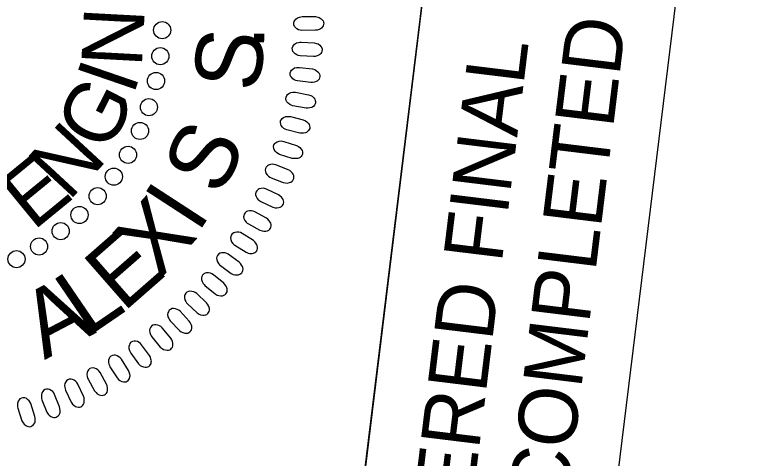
# Model space of a CAD drawing. Extents: x 480570 to 481861, y 488765 to 490569.
# Drawn here: x 480900.2 to 480970.2, y 490446 to 490487.4 of the extents above; entities that cross this region are included whole.
import ezdxf

# ---------------------------------------------------------------- set-up
doc = ezdxf.new("R2010")
doc.units = 0
for name, color, linetype in [('Sheet PE Seal Cell', 7, 'Continuous'), ('Sheet Plan CELL', 7, 'Continuous'), ('Sheet Sticker Exception Certification CELL', 7, 'Continuous')]:
    doc.layers.add(name, color=color, linetype=linetype)

msp = doc.modelspace()

# ---------------------------------------------------------------- linework, layer by layer
at = {"layer": 'Sheet PE Seal Cell'}
for points in [[(480927.001, 490487.259), (480928.228, 490487.263), (480928.447, 490487.227), (480928.587, 490487.176), (480928.758, 490487.064), (480928.867, 490486.967), (480928.948, 490486.855), (480928.988, 490486.751), (480929.008, 490486.638), (480928.988, 490486.527), (480928.959, 490486.407), (480928.9, 490486.302), (480928.8, 490486.197), (480928.721, 490486.137), (480928.571, 490486.069), (480928.392, 490486.008), (480928.233, 490485.985), (480926.976, 490485.973), (480926.807, 490485.995), (480926.667, 490486.04), (480926.507, 490486.129), (480926.367, 490486.239), (480926.286, 490486.337), (480926.226, 490486.494), (480926.206, 490486.644), (480926.245, 490486.793), (480926.295, 490486.898), (480926.394, 490487.025), (480926.562, 490487.145), (480926.743, 490487.213), (480926.871, 490487.243)], [(480926.906, 490484.887), (480928.131, 490484.814), (480928.348, 490484.765), (480928.484, 490484.705), (480928.647, 490484.582), (480928.751, 490484.479), (480928.824, 490484.362), (480928.857, 490484.256), (480928.87, 490484.142), (480928.844, 490484.032), (480928.807, 490483.914), (480928.741, 490483.813), (480928.635, 490483.714), (480928.552, 490483.659), (480928.399, 490483.601), (480928.216, 490483.552), (480928.055, 490483.539), (480926.801, 490483.605), (480926.633, 490483.638), (480926.496, 490483.691), (480926.342, 490483.791), (480926.209, 490483.91), (480926.136, 490484.012), (480926.085, 490484.172), (480926.074, 490484.323), (480926.123, 490484.469), (480926.179, 490484.571), (480926.285, 490484.692), (480926.462, 490484.801), (480926.645, 490484.858), (480926.776, 490484.88)], [(480926.741, 490482.523), (480927.959, 490482.373), (480928.171, 490482.31), (480928.304, 490482.241), (480928.459, 490482.109), (480928.556, 490481.999), (480928.622, 490481.878), (480928.648, 490481.77), (480928.654, 490481.656), (480928.621, 490481.547), (480928.577, 490481.432), (480928.505, 490481.335), (480928.393, 490481.243), (480928.306, 490481.194), (480928.149, 490481.145), (480927.964, 490481.107), (480927.803, 490481.105), (480926.555, 490481.25), (480926.39, 490481.293), (480926.256, 490481.355), (480926.109, 490481.463), (480925.984, 490481.591), (480925.916, 490481.698), (480925.876, 490481.861), (480925.875, 490482.012), (480925.932, 490482.155), (480925.995, 490482.253), (480926.109, 490482.368), (480926.292, 490482.465), (480926.479, 490482.51), (480926.611, 490482.523)], [(480926.384, 490480.196), (480927.59, 490479.97), (480927.798, 490479.893), (480927.927, 490479.816), (480928.073, 490479.675), (480928.163, 490479.559), (480928.22, 490479.435), (480928.241, 490479.324), (480928.239, 490479.209), (480928.199, 490479.104), (480928.148, 490478.992), (480928.07, 490478.9), (480927.952, 490478.815), (480927.863, 490478.771), (480927.704, 490478.732), (480927.516, 490478.706), (480927.355, 490478.714), (480926.119, 490478.937), (480925.956, 490478.99), (480925.827, 490479.06), (480925.687, 490479.178), (480925.57, 490479.313), (480925.51, 490479.424), (480925.48, 490479.589), (480925.488, 490479.74), (480925.555, 490479.88), (480925.623, 490479.973), (480925.744, 490480.08), (480925.933, 490480.166), (480926.122, 490480.199), (480926.254, 490480.204)], [(480925.907, 490477.919), (480927.096, 490477.619), (480927.3, 490477.529), (480927.423, 490477.444), (480927.56, 490477.294), (480927.642, 490477.172), (480927.692, 490477.044), (480927.705, 490476.933), (480927.697, 490476.819), (480927.65, 490476.716), (480927.592, 490476.607), (480927.508, 490476.52), (480927.385, 490476.444), (480927.293, 490476.405), (480927.132, 490476.376), (480926.943, 490476.362), (480926.783, 490476.379), (480925.563, 490476.68), (480925.405, 490476.743), (480925.28, 490476.822), (480925.147, 490476.947), (480925.039, 490477.09), (480924.986, 490477.204), (480924.966, 490477.371), (480924.984, 490477.521), (480925.059, 490477.656), (480925.133, 490477.745), (480925.261, 490477.844), (480925.454, 490477.918), (480925.645, 490477.939), (480925.778, 490477.937)], [(480925.296, 490475.61), (480926.465, 490475.235), (480926.662, 490475.133), (480926.779, 490475.041), (480926.906, 490474.882), (480926.981, 490474.756), (480927.023, 490474.625), (480927.029, 490474.513), (480927.013, 490474.4), (480926.96, 490474.3), (480926.895, 490474.195), (480926.806, 490474.113), (480926.679, 490474.044), (480926.585, 490474.012), (480926.422, 490473.993), (480926.233, 490473.991), (480926.074, 490474.018), (480924.875, 490474.395), (480924.72, 490474.469), (480924.602, 490474.554), (480924.477, 490474.688), (480924.378, 490474.837), (480924.332, 490474.954), (480924.323, 490475.122), (480924.35, 490475.271), (480924.434, 490475.4), (480924.513, 490475.485), (480924.646, 490475.576), (480924.844, 490475.637), (480925.036, 490475.647), (480925.168, 490475.635)], [(480924.087, 490472.21), (480925.23, 490471.762), (480925.447, 490471.718), (480925.596, 490471.715), (480925.796, 490471.758), (480925.933, 490471.808), (480926.048, 490471.884), (480926.124, 490471.966), (480926.183, 490472.063), (480926.205, 490472.175), (480926.22, 490472.298), (480926.204, 490472.416), (480926.149, 490472.55), (480926.097, 490472.635), (480925.981, 490472.752), (480925.836, 490472.874), (480925.695, 490472.953), (480924.528, 490473.418), (480924.362, 490473.459), (480924.216, 490473.467), (480924.034, 490473.442), (480923.864, 490473.389), (480923.754, 490473.327), (480923.641, 490473.203), (480923.568, 490473.071), (480923.55, 490472.917), (480923.559, 490472.802), (480923.605, 490472.647), (480923.72, 490472.474), (480923.863, 490472.346), (480923.972, 490472.271)], [(480923.136, 490469.976), (480924.248, 490469.458), (480924.463, 490469.399), (480924.612, 490469.387), (480924.813, 490469.417), (480924.953, 490469.459), (480925.073, 490469.527), (480925.153, 490469.605), (480925.219, 490469.698), (480925.248, 490469.808), (480925.271, 490469.93), (480925.262, 490470.049), (480925.215, 490470.187), (480925.168, 490470.274), (480925.061, 490470.399), (480924.923, 490470.528), (480924.788, 490470.616), (480923.653, 490471.154), (480923.489, 490471.205), (480923.343, 490471.223), (480923.161, 490471.209), (480922.988, 490471.167), (480922.874, 490471.112), (480922.753, 490470.996), (480922.672, 490470.868), (480922.645, 490470.716), (480922.647, 490470.6), (480922.683, 490470.443), (480922.786, 490470.263), (480922.921, 490470.126), (480923.025, 490470.044)], [(480921.973, 490467.893), (480923.05, 490467.306), (480923.261, 490467.234), (480923.408, 490467.212), (480923.611, 490467.23), (480923.754, 490467.263), (480923.877, 490467.324), (480923.963, 490467.396), (480924.034, 490467.485), (480924.07, 490467.593), (480924.101, 490467.713), (480924.099, 490467.833), (480924.061, 490467.972), (480924.019, 490468.063), (480923.92, 490468.194), (480923.791, 490468.332), (480923.662, 490468.429), (480922.562, 490469.036), (480922.403, 490469.098), (480922.258, 490469.124), (480922.076, 490469.122), (480921.899, 490469.091), (480921.782, 490469.043), (480921.655, 490468.935), (480921.566, 490468.812), (480921.53, 490468.662), (480921.524, 490468.546), (480921.55, 490468.387), (480921.642, 490468.201), (480921.767, 490468.056), (480921.867, 490467.968)], [(480920.714, 490465.903), (480921.752, 490465.25), (480921.958, 490465.165), (480922.104, 490465.135), (480922.307, 490465.139), (480922.452, 490465.163), (480922.579, 490465.215), (480922.668, 490465.282), (480922.745, 490465.367), (480922.788, 490465.473), (480922.826, 490465.59), (480922.831, 490465.71), (480922.803, 490465.852), (480922.767, 490465.945), (480922.676, 490466.082), (480922.557, 490466.228), (480922.433, 490466.332), (480921.374, 490467.008), (480921.218, 490467.079), (480921.076, 490467.115), (480920.893, 490467.125), (480920.715, 490467.104), (480920.596, 490467.064), (480920.462, 490466.963), (480920.365, 490466.847), (480920.319, 490466.7), (480920.306, 490466.584), (480920.322, 490466.424), (480920.402, 490466.233), (480920.519, 490466.079), (480920.612, 490465.986)], [(480919.366, 490463.993), (480920.361, 490463.276), (480920.561, 490463.178), (480920.705, 490463.139), (480920.908, 490463.131), (480921.054, 490463.145), (480921.184, 490463.19), (480921.278, 490463.251), (480921.36, 490463.331), (480921.408, 490463.433), (480921.454, 490463.547), (480921.468, 490463.667), (480921.447, 490463.811), (480921.418, 490463.905), (480921.336, 490464.048), (480921.225, 490464.201), (480921.109, 490464.313), (480920.093, 490465.054), (480919.943, 490465.134), (480919.803, 490465.18), (480919.622, 490465.2), (480919.443, 490465.191), (480919.321, 490465.159), (480919.181, 490465.067), (480919.077, 490464.957), (480919.022, 490464.813), (480919.001, 490464.698), (480919.008, 490464.537), (480919.076, 490464.341), (480919.182, 490464.181), (480919.269, 490464.081)], [(480917.914, 490462.138), (480918.863, 490461.359), (480919.056, 490461.249), (480919.197, 490461.201), (480919.4, 490461.179), (480919.546, 490461.185), (480919.678, 490461.222), (480919.776, 490461.276), (480919.862, 490461.351), (480919.918, 490461.45), (480919.971, 490461.562), (480919.991, 490461.68), (480919.981, 490461.825), (480919.957, 490461.922), (480919.884, 490462.069), (480919.783, 490462.228), (480919.674, 490462.347), (480918.708, 490463.15), (480918.562, 490463.24), (480918.426, 490463.294), (480918.246, 490463.326), (480918.067, 490463.328), (480917.943, 490463.303), (480917.797, 490463.221), (480917.687, 490463.117), (480917.623, 490462.976), (480917.595, 490462.864), (480917.591, 490462.703), (480917.646, 490462.503), (480917.743, 490462.336), (480917.824, 490462.231)], [(480916.281, 490460.421), (480917.179, 490459.585), (480917.365, 490459.463), (480917.503, 490459.406), (480917.703, 490459.372), (480917.85, 490459.369), (480917.985, 490459.396), (480918.085, 490459.445), (480918.176, 490459.514), (480918.238, 490459.61), (480918.297, 490459.718), (480918.326, 490459.835), (480918.323, 490459.98), (480918.306, 490460.078), (480918.242, 490460.229), (480918.152, 490460.395), (480918.051, 490460.52), (480917.136, 490461.382), (480916.997, 490461.482), (480916.864, 490461.544), (480916.687, 490461.587), (480916.508, 490461.601), (480916.383, 490461.584), (480916.232, 490461.51), (480916.115, 490461.414), (480916.043, 490461.277), (480916.009, 490461.166), (480915.994, 490461.006), (480916.037, 490460.803), (480916.123, 490460.631), (480916.197, 490460.521)], [(480914.675, 490458.824), (480915.518, 490457.932), (480915.696, 490457.799), (480915.83, 490457.733), (480916.028, 490457.687), (480916.174, 490457.675), (480916.31, 490457.693), (480916.414, 490457.736), (480916.51, 490457.799), (480916.576, 490457.89), (480916.643, 490457.994), (480916.678, 490458.109), (480916.685, 490458.254), (480916.674, 490458.353), (480916.62, 490458.508), (480916.54, 490458.679), (480916.447, 490458.811), (480915.588, 490459.729), (480915.456, 490459.837), (480915.326, 490459.907), (480915.152, 490459.961), (480914.975, 490459.986), (480914.849, 490459.977), (480914.694, 490459.912), (480914.572, 490459.824), (480914.491, 490459.692), (480914.449, 490459.584), (480914.425, 490459.424), (480914.455, 490459.219), (480914.529, 490459.042), (480914.597, 490458.928)], [(480912.951, 490457.332), (480913.737, 490456.389), (480913.906, 490456.245), (480914.035, 490456.171), (480914.23, 490456.113), (480914.376, 490456.09), (480914.512, 490456.101), (480914.618, 490456.137), (480914.717, 490456.194), (480914.79, 490456.281), (480914.863, 490456.381), (480914.905, 490456.493), (480914.921, 490456.637), (480914.917, 490456.736), (480914.873, 490456.895), (480914.803, 490457.071), (480914.719, 490457.208), (480913.919, 490458.178), (480913.794, 490458.294), (480913.67, 490458.372), (480913.499, 490458.437), (480913.324, 490458.473), (480913.198, 490458.472), (480913.039, 490458.418), (480912.911, 490458.337), (480912.822, 490458.21), (480912.774, 490458.105), (480912.739, 490457.947), (480912.756, 490457.741), (480912.82, 490457.559), (480912.88, 490457.44)], [(480910.975, 490455.825), (480911.7, 490454.835), (480911.86, 490454.68), (480911.984, 490454.598), (480912.175, 490454.527), (480912.318, 490454.497), (480912.456, 490454.499), (480912.564, 490454.528), (480912.666, 490454.578), (480912.745, 490454.661), (480912.824, 490454.756), (480912.873, 490454.865), (480912.898, 490455.008), (480912.9, 490455.107), (480912.866, 490455.268), (480912.808, 490455.448), (480912.732, 490455.59), (480911.995, 490456.608), (480911.877, 490456.732), (480911.758, 490456.818), (480911.592, 490456.894), (480911.419, 490456.941), (480911.293, 490456.947), (480911.131, 490456.903), (480910.999, 490456.83), (480910.902, 490456.71), (480910.847, 490456.608), (480910.803, 490456.452), (480910.807, 490456.245), (480910.859, 490456.06), (480910.911, 490455.938)], [(480909.035, 490454.541), (480909.696, 490453.507), (480909.846, 490453.343), (480909.965, 490453.253), (480910.151, 490453.171), (480910.292, 490453.131), (480910.429, 490453.124), (480910.539, 490453.147), (480910.644, 490453.191), (480910.727, 490453.268), (480910.812, 490453.358), (480910.868, 490453.464), (480910.902, 490453.604), (480910.91, 490453.704), (480910.886, 490453.867), (480910.839, 490454.05), (480910.773, 490454.196), (480910.102, 490455.259), (480909.992, 490455.39), (480909.878, 490455.483), (480909.717, 490455.569), (480909.547, 490455.626), (480909.422, 490455.641), (480909.258, 490455.607), (480909.121, 490455.543), (480909.017, 490455.429), (480908.956, 490455.33), (480908.902, 490455.178), (480908.892, 490454.971), (480908.933, 490454.783), (480908.978, 490454.658)], [(480906.997, 490453.376), (480907.592, 490452.303), (480907.731, 490452.129), (480907.844, 490452.032), (480908.025, 490451.938), (480908.163, 490451.89), (480908.3, 490451.875), (480908.41, 490451.89), (480908.519, 490451.927), (480908.607, 490451.999), (480908.697, 490452.083), (480908.76, 490452.186), (480908.802, 490452.324), (480908.816, 490452.423), (480908.803, 490452.587), (480908.768, 490452.772), (480908.71, 490452.923), (480908.107, 490454.025), (480908.005, 490454.163), (480907.898, 490454.263), (480907.742, 490454.359), (480907.577, 490454.427), (480907.453, 490454.45), (480907.287, 490454.426), (480907.146, 490454.37), (480907.035, 490454.263), (480906.968, 490454.169), (480906.904, 490454.02), (480906.883, 490453.814), (480906.911, 490453.624), (480906.947, 490453.496)], [(480904.882, 490452.349), (480905.409, 490451.24), (480905.536, 490451.058), (480905.643, 490450.954), (480905.818, 490450.849), (480905.952, 490450.792), (480906.088, 490450.768), (480906.199, 490450.777), (480906.309, 490450.807), (480906.402, 490450.874), (480906.497, 490450.952), (480906.566, 490451.05), (480906.618, 490451.186), (480906.637, 490451.283), (480906.634, 490451.447), (480906.611, 490451.635), (480906.563, 490451.788), (480906.03, 490452.927), (480905.938, 490453.07), (480905.836, 490453.177), (480905.687, 490453.283), (480905.526, 490453.361), (480905.404, 490453.391), (480905.236, 490453.378), (480905.093, 490453.332), (480904.975, 490453.232), (480904.902, 490453.142), (480904.83, 490452.997), (480904.795, 490452.793), (480904.811, 490452.601), (480904.84, 490452.472)], [(480902.682, 490451.452), (480903.138, 490450.313), (480903.254, 490450.124), (480903.355, 490450.013), (480903.522, 490449.897), (480903.653, 490449.831), (480903.786, 490449.799), (480903.899, 490449.801), (480904.01, 490449.824), (480904.106, 490449.885), (480904.207, 490449.957), (480904.281, 490450.051), (480904.342, 490450.183), (480904.368, 490450.279), (480904.374, 490450.443), (480904.363, 490450.632), (480904.325, 490450.788), (480903.865, 490451.958), (480903.781, 490452.107), (480903.687, 490452.22), (480903.545, 490452.334), (480903.389, 490452.422), (480903.269, 490452.46), (480903.101, 490452.457), (480902.954, 490452.42), (480902.831, 490452.328), (480902.752, 490452.243), (480902.671, 490452.103), (480902.623, 490451.901), (480902.627, 490451.709), (480902.648, 490451.578)], [(480900.422, 490450.673), (480900.806, 490449.508), (480900.91, 490449.311), (480901.003, 490449.194), (480901.163, 490449.069), (480901.29, 490448.995), (480901.421, 490448.954), (480901.533, 490448.949), (480901.646, 490448.965), (480901.745, 490449.019), (480901.85, 490449.085), (480901.931, 490449.175), (480901.999, 490449.302), (480902.031, 490449.396), (480902.048, 490449.56), (480902.048, 490449.749), (480902.02, 490449.907), (480901.635, 490451.104), (480901.56, 490451.258), (480901.474, 490451.376), (480901.339, 490451.499), (480901.189, 490451.598), (480901.071, 490451.643), (480900.903, 490451.651), (480900.755, 490451.623), (480900.626, 490451.538), (480900.542, 490451.458), (480900.452, 490451.324), (480900.392, 490451.125), (480900.384, 490450.933), (480900.396, 490450.801)]]:
    msp.add_lwpolyline(points, close=True, dxfattribs=at)
for centre in [(480913.917, 490485.995), (480913.74, 490483.569), (480913.336, 490481.252), (480912.675, 490478.806), (480911.84, 490476.582), (480910.724, 490474.352), (480909.39, 490472.31), (480907.883, 490470.489), (480906.182, 490468.732), (480904.432, 490467.221), (480902.41, 490465.785), (480900.298, 490464.599)]:
    msp.add_circle(centre, 0.801, dxfattribs=at)
at = {"layer": 'Sheet Plan CELL'}
for points in [[(480819.562, 490445.095), (480831.672, 490544.346), (480943.356, 490530.718), (480931.245, 490431.454)], [(481654.799, 488932.664), (480612.566, 489059.935), (480770.135, 490350.338), (480919.092, 490332.157), (480943.356, 490530.718), (481836.655, 490421.612)]]:
    msp.add_lwpolyline(points, close=True, dxfattribs=at)
at = {"layer": 'Sheet Sticker Exception Certification CELL'}
for p, q in [((480919.092, 490332.157), (480943.344, 490530.719)), ((480919.092, 490332.157), (480943.344, 490530.719)), ((480966.67, 490527.87), (480942.419, 490329.308)), ((480966.67, 490527.87), (480942.419, 490329.308))]:
    msp.add_line(p, q, dxfattribs=at)

# ---------------------------------------------------------------- texts
at = {"layer": 'Sheet PE Seal Cell'}
for s, height, rotation, p in [('N', 5.669, 86.93731, (480912.003, 490482.476)), ('S', 6.236, 82.41555, (480922.893, 490480.105)), ('.', 6.236, 89.2612, (480923.432, 490484.109)), ('I', 5.669, 71.05771, (480911.2, 490479.8)), ('G', 5.669, 63.11791, (480908.84, 490474.419)), ('N', 5.669, 47.23832, (480905.171, 490469.936)), ('S', 6.236, 63.82035, (480919.36, 490470.341)), ('E', 5.669, 39.29852, (480901.857, 490467.183)), ('I', 6.236, 56.97469, (480917.235, 490466.918)), ('X', 6.236, 48.02737, (480913.621, 490462.575)), ('E', 6.236, 41.18171, (480910.258, 490459.559)), ('L', 6.236, 34.33605, (480906.87, 490457.24)), ('A', 6.236, 27.71638, (480902.909, 490455.165))]:
    msp.add_text(s, height=height, rotation=rotation, dxfattribs=at).set_placement(p)
at = {"layer": 'Sheet Sticker Exception Certification CELL'}
for s, p in [('UNLESS ALL SIGNATURES COMPLETED', (480940.036, 490345.718)), ('UNLESS ALL SIGNATURES COMPLETED', (480940.036, 490345.718)), ('DOCUMENT NOT CONSIDERED FINAL', (480931.916, 490351.819)), ('DOCUMENT NOT CONSIDERED FINAL', (480931.916, 490351.819))]:
    msp.add_text(s, height=5.5, rotation=83.03651, dxfattribs=at).set_placement(p)

doc.saveas('drawing.dxf')
